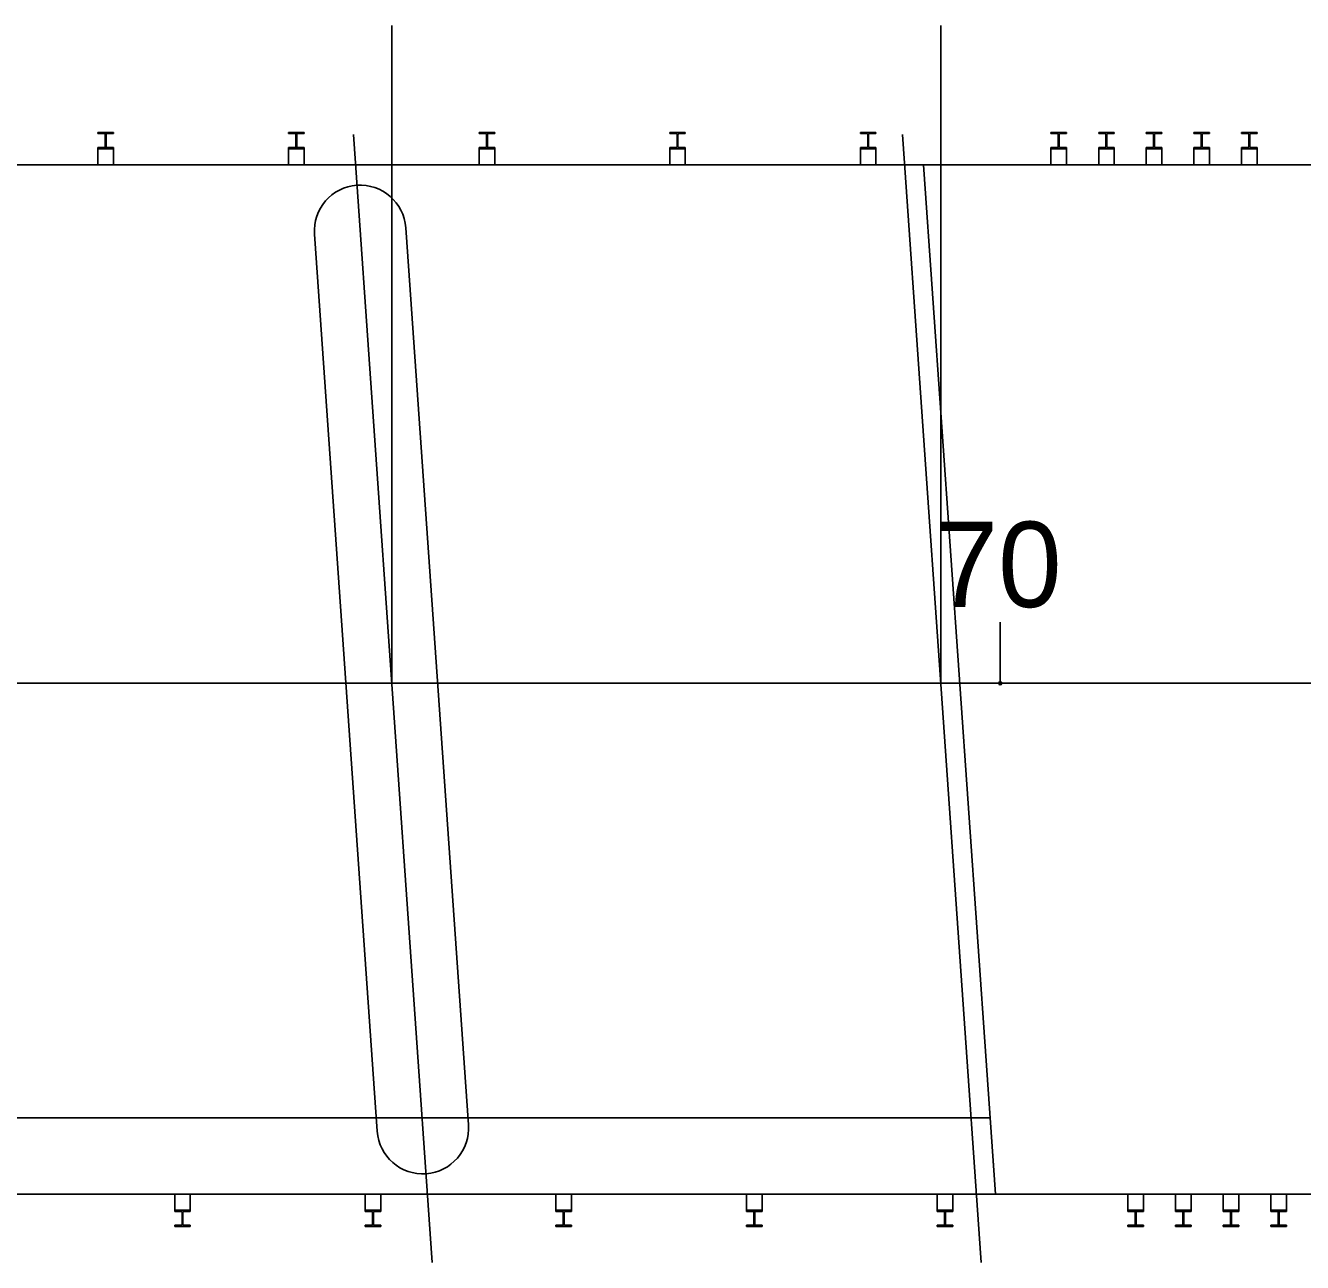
# Model space of a CAD drawing. Extents: x 27625 to 127752, y 6088 to 302357.
# Drawn here: x 27875.45 to 27917.32, y 6087.66 to 6128.23 of the extents above; entities that cross this region are included whole.
import ezdxf

# ---------------------------------------------------------------- set-up
doc = ezdxf.new("R2010")
doc.units = 0
for name, color, linetype in [('_CIVIL_CONSTRUCTION', 7, 'Continuous'), ('DR_X_Cells', 7, 'Continuous'), ('DV_X_Property_Line', 7, 'Continuous'), ('DV_X_Section_VMS_Line', 7, 'Continuous'), ('RS_Raster1', 7, 'Continuous'), ('RW_X_CL', 7, 'Continuous'), ('RW_X_CL_100_Bearings', 7, 'Continuous'), ('RW_X_CL_100_Curve_Data', 7, 'Continuous'), ('RW_X_CL_100_Stations', 7, 'Continuous'), ('RW_X_Fee_RW', 7, 'Continuous'), ('SV_X_Shot_Marker', 7, 'Continuous'), ('TopoDOT_Transients', 7, 'Continuous')]:
    doc.layers.add(name, color=color, linetype=linetype)

msp = doc.modelspace()

# ---------------------------------------------------------------- linework, layer by layer
at = {"layer": '_CIVIL_CONSTRUCTION'}
for p, q in [((27887.46, 6106.658), (27887.46, 6128.23)), ((27905.46, 6106.658), (27905.46, 6128.23))]:
    msp.add_line(p, q, dxfattribs=at)
at = {"layer": 'DR_X_Cells'}
msp.add_line((27907.411, 6106.658), (27907.411, 6108.658), dxfattribs=at)
msp.add_line((27907.411, 6106.658), (27907.411, 6108.658), dxfattribs=at)
at = {"layer": 'DV_X_Property_Line'}
for p, q in [((27904.895, 6123.658), (27845.148, 6123.658)), ((27907.255, 6089.908), (27847.508, 6089.908))]:
    msp.add_line(p, q, dxfattribs=at)
at = {"layer": 'DV_X_Section_VMS_Line'}
msp.add_line((27905.46, 6106.658), (27832.372, 6106.658), dxfattribs=at)
at = {"layer": 'RS_Raster1'}
msp.add_circle((27907.411, 6106.658), 0.05, dxfattribs=at)
at = {"layer": 'RW_X_CL'}
for p, q in [((27887.919, 6121.6), (27889.977, 6092.176)), ((27884.926, 6121.39), (27886.984, 6091.966))]:
    msp.add_line(p, q, dxfattribs=at)
for centre, start, end in [((27886.423, 6121.495), 4, 184), ((27888.48, 6092.071), 184, 4)]:
    msp.add_arc(centre, 1.5, start, end, dxfattribs=at)
at = {"layer": 'RW_X_CL_100_Bearings'}
for p, q in [((27904.895, 6123.658), (27907.255, 6089.908)), ((27904.895, 6123.658), (27919.895, 6123.658)), ((27907.255, 6089.908), (27922.255, 6089.908))]:
    msp.add_line(p, q, dxfattribs=at)
at = {"layer": 'RW_X_CL_100_Curve_Data'}
for p, q in [((27877.825, 6124.72), (27878.336, 6124.72)), ((27877.825, 6124.72), (27877.825, 6124.684)), ((27877.825, 6124.684), (27878.034, 6124.684)), ((27878.065, 6124.653), (27878.065, 6124.257)), ((27878.096, 6124.653), (27878.096, 6124.257)), ((27878.127, 6124.684), (27878.336, 6124.684)), ((27878.336, 6124.72), (27878.336, 6124.684)), ((27884.075, 6124.72), (27884.586, 6124.72)), ((27884.075, 6124.72), (27884.075, 6124.684)), ((27884.075, 6124.684), (27884.284, 6124.684)), ((27884.315, 6124.653), (27884.315, 6124.257)), ((27884.346, 6124.653), (27884.346, 6124.257)), ((27884.377, 6124.684), (27884.586, 6124.684)), ((27884.586, 6124.72), (27884.586, 6124.684)), ((27890.325, 6124.72), (27890.836, 6124.72)), ((27890.325, 6124.72), (27890.325, 6124.684)), ((27890.325, 6124.684), (27890.534, 6124.684)), ((27890.565, 6124.653), (27890.565, 6124.257)), ((27890.596, 6124.653), (27890.596, 6124.257)), ((27890.627, 6124.684), (27890.836, 6124.684)), ((27890.836, 6124.72), (27890.836, 6124.684)), ((27896.575, 6124.72), (27897.086, 6124.72)), ((27896.575, 6124.72), (27896.575, 6124.684)), ((27896.575, 6124.684), (27896.784, 6124.684)), ((27896.815, 6124.653), (27896.815, 6124.257)), ((27896.846, 6124.653), (27896.846, 6124.257)), ((27896.877, 6124.684), (27897.086, 6124.684)), ((27897.086, 6124.72), (27897.086, 6124.684)), ((27902.825, 6124.72), (27903.336, 6124.72)), ((27902.825, 6124.72), (27902.825, 6124.684)), ((27902.825, 6124.684), (27903.034, 6124.684)), ((27903.065, 6124.653), (27903.065, 6124.257)), ((27903.096, 6124.653), (27903.096, 6124.257)), ((27903.127, 6124.684), (27903.336, 6124.684)), ((27903.336, 6124.72), (27903.336, 6124.684)), ((27909.075, 6124.72), (27909.586, 6124.72)), ((27909.075, 6124.72), (27909.075, 6124.684)), ((27909.075, 6124.684), (27909.284, 6124.684)), ((27909.315, 6124.653), (27909.315, 6124.257)), ((27909.346, 6124.653), (27909.346, 6124.257)), ((27909.377, 6124.684), (27909.586, 6124.684)), ((27909.586, 6124.72), (27909.586, 6124.684)), ((27910.638, 6124.72), (27911.148, 6124.72)), ((27910.638, 6124.72), (27910.638, 6124.684)), ((27910.638, 6124.684), (27910.846, 6124.684)), ((27910.877, 6124.653), (27910.877, 6124.257)), ((27910.909, 6124.653), (27910.909, 6124.257)), ((27910.94, 6124.684), (27911.148, 6124.684)), ((27911.148, 6124.72), (27911.148, 6124.684)), ((27912.2, 6124.72), (27912.711, 6124.72)), ((27912.2, 6124.72), (27912.2, 6124.684)), ((27912.2, 6124.684), (27912.409, 6124.684)), ((27912.44, 6124.653), (27912.44, 6124.257)), ((27912.471, 6124.653), (27912.471, 6124.257)), ((27912.502, 6124.684), (27912.711, 6124.684)), ((27912.711, 6124.72), (27912.711, 6124.684)), ((27913.763, 6124.72), (27914.273, 6124.72)), ((27913.763, 6124.72), (27913.763, 6124.684)), ((27913.763, 6124.684), (27913.971, 6124.684)), ((27914.002, 6124.653), (27914.002, 6124.257)), ((27914.034, 6124.653), (27914.034, 6124.257)), ((27914.065, 6124.684), (27914.273, 6124.684)), ((27914.273, 6124.72), (27914.273, 6124.684)), ((27915.325, 6124.72), (27915.836, 6124.72)), ((27915.325, 6124.72), (27915.325, 6124.684)), ((27915.325, 6124.684), (27915.534, 6124.684)), ((27915.565, 6124.653), (27915.565, 6124.257)), ((27915.596, 6124.653), (27915.596, 6124.257)), ((27915.627, 6124.684), (27915.836, 6124.684)), ((27915.836, 6124.72), (27915.836, 6124.684)), ((27877.825, 6124.226), (27877.825, 6124.189)), ((27877.825, 6124.226), (27878.034, 6124.226)), ((27877.825, 6124.189), (27878.336, 6124.189)), ((27877.825, 6124.189), (27877.825, 6123.658)), ((27878.127, 6124.226), (27878.336, 6124.226)), ((27878.336, 6124.226), (27878.336, 6124.189)), ((27878.336, 6123.658), (27878.336, 6124.189)), ((27884.075, 6124.226), (27884.075, 6124.189)), ((27884.075, 6124.226), (27884.284, 6124.226)), ((27884.075, 6124.189), (27884.586, 6124.189)), ((27884.075, 6124.189), (27884.075, 6123.658)), ((27884.377, 6124.226), (27884.586, 6124.226)), ((27884.586, 6124.226), (27884.586, 6124.189)), ((27884.586, 6123.658), (27884.586, 6124.189)), ((27890.325, 6124.226), (27890.325, 6124.189)), ((27890.325, 6124.226), (27890.534, 6124.226)), ((27890.325, 6124.189), (27890.836, 6124.189)), ((27890.325, 6124.189), (27890.325, 6123.658)), ((27890.627, 6124.226), (27890.836, 6124.226)), ((27890.836, 6124.226), (27890.836, 6124.189)), ((27890.836, 6123.658), (27890.836, 6124.189)), ((27896.575, 6124.226), (27896.575, 6124.189)), ((27896.575, 6124.226), (27896.784, 6124.226)), ((27896.575, 6124.189), (27897.086, 6124.189)), ((27896.575, 6124.189), (27896.575, 6123.658)), ((27896.877, 6124.226), (27897.086, 6124.226)), ((27897.086, 6124.226), (27897.086, 6124.189)), ((27897.086, 6123.658), (27897.086, 6124.189)), ((27902.825, 6124.226), (27902.825, 6124.189)), ((27902.825, 6124.226), (27903.034, 6124.226)), ((27902.825, 6124.189), (27903.336, 6124.189)), ((27902.825, 6124.189), (27902.825, 6123.658)), ((27903.127, 6124.226), (27903.336, 6124.226)), ((27903.336, 6124.226), (27903.336, 6124.189)), ((27903.336, 6123.658), (27903.336, 6124.189)), ((27909.075, 6124.226), (27909.075, 6124.189)), ((27909.075, 6124.226), (27909.284, 6124.226)), ((27909.075, 6124.189), (27909.586, 6124.189)), ((27909.075, 6124.189), (27909.075, 6123.658)), ((27909.377, 6124.226), (27909.586, 6124.226)), ((27909.586, 6124.226), (27909.586, 6124.189)), ((27909.586, 6123.658), (27909.586, 6124.189)), ((27910.638, 6124.226), (27910.638, 6124.189)), ((27910.638, 6124.226), (27910.846, 6124.226)), ((27910.638, 6124.189), (27911.148, 6124.189)), ((27910.638, 6124.189), (27910.638, 6123.658)), ((27910.94, 6124.226), (27911.148, 6124.226)), ((27911.148, 6124.226), (27911.148, 6124.189)), ((27911.148, 6123.658), (27911.148, 6124.189)), ((27912.2, 6124.226), (27912.2, 6124.189)), ((27912.2, 6124.226), (27912.409, 6124.226)), ((27912.2, 6124.189), (27912.711, 6124.189)), ((27912.2, 6124.189), (27912.2, 6123.658)), ((27912.502, 6124.226), (27912.711, 6124.226)), ((27912.711, 6124.226), (27912.711, 6124.189)), ((27912.711, 6123.658), (27912.711, 6124.189)), ((27913.763, 6124.226), (27913.763, 6124.189)), ((27913.763, 6124.226), (27913.971, 6124.226)), ((27913.763, 6124.189), (27914.273, 6124.189)), ((27913.763, 6124.189), (27913.763, 6123.658)), ((27914.065, 6124.226), (27914.273, 6124.226)), ((27914.273, 6124.226), (27914.273, 6124.189)), ((27914.273, 6123.658), (27914.273, 6124.189)), ((27915.325, 6124.226), (27915.325, 6124.189)), ((27915.325, 6124.226), (27915.534, 6124.226)), ((27915.325, 6124.189), (27915.836, 6124.189)), ((27915.325, 6124.189), (27915.325, 6123.658)), ((27915.627, 6124.226), (27915.836, 6124.226)), ((27915.836, 6124.226), (27915.836, 6124.189)), ((27915.836, 6123.658), (27915.836, 6124.189)), ((27880.345, 6089.377), (27880.345, 6089.908)), ((27880.856, 6089.908), (27880.856, 6089.377)), ((27886.595, 6089.377), (27886.595, 6089.908)), ((27887.106, 6089.908), (27887.106, 6089.377)), ((27892.845, 6089.377), (27892.845, 6089.908)), ((27893.356, 6089.908), (27893.356, 6089.377)), ((27899.095, 6089.377), (27899.095, 6089.908)), ((27899.606, 6089.908), (27899.606, 6089.377)), ((27905.345, 6089.377), (27905.345, 6089.908)), ((27905.856, 6089.908), (27905.856, 6089.377)), ((27911.595, 6089.377), (27911.595, 6089.908)), ((27912.106, 6089.908), (27912.106, 6089.377)), ((27913.158, 6089.377), (27913.158, 6089.908)), ((27913.668, 6089.908), (27913.668, 6089.377)), ((27914.72, 6089.377), (27914.72, 6089.908)), ((27915.231, 6089.908), (27915.231, 6089.377)), ((27916.283, 6089.377), (27916.283, 6089.908)), ((27916.793, 6089.908), (27916.793, 6089.377)), ((27880.345, 6089.377), (27880.856, 6089.377)), ((27880.345, 6089.34), (27880.345, 6089.377)), ((27880.345, 6089.34), (27880.554, 6089.34)), ((27880.585, 6088.913), (27880.585, 6089.309)), ((27880.616, 6088.913), (27880.616, 6089.309)), ((27880.647, 6089.34), (27880.856, 6089.34)), ((27880.856, 6089.34), (27880.856, 6089.377)), ((27886.595, 6089.377), (27887.106, 6089.377)), ((27886.595, 6089.34), (27886.595, 6089.377)), ((27886.595, 6089.34), (27886.804, 6089.34)), ((27886.835, 6088.913), (27886.835, 6089.309)), ((27886.866, 6088.913), (27886.866, 6089.309)), ((27886.897, 6089.34), (27887.106, 6089.34)), ((27887.106, 6089.34), (27887.106, 6089.377)), ((27892.845, 6089.377), (27893.356, 6089.377)), ((27892.845, 6089.34), (27892.845, 6089.377)), ((27892.845, 6089.34), (27893.054, 6089.34)), ((27893.085, 6088.913), (27893.085, 6089.309)), ((27893.116, 6088.913), (27893.116, 6089.309)), ((27893.147, 6089.34), (27893.356, 6089.34)), ((27893.356, 6089.34), (27893.356, 6089.377)), ((27899.095, 6089.377), (27899.606, 6089.377)), ((27899.095, 6089.34), (27899.095, 6089.377)), ((27899.095, 6089.34), (27899.304, 6089.34)), ((27899.335, 6088.913), (27899.335, 6089.309)), ((27899.366, 6088.913), (27899.366, 6089.309)), ((27899.397, 6089.34), (27899.606, 6089.34)), ((27899.606, 6089.34), (27899.606, 6089.377)), ((27905.345, 6089.377), (27905.856, 6089.377)), ((27905.345, 6089.34), (27905.345, 6089.377)), ((27905.345, 6089.34), (27905.554, 6089.34)), ((27905.585, 6088.913), (27905.585, 6089.309)), ((27905.616, 6088.913), (27905.616, 6089.309)), ((27905.647, 6089.34), (27905.856, 6089.34)), ((27905.856, 6089.34), (27905.856, 6089.377)), ((27911.595, 6089.377), (27912.106, 6089.377)), ((27911.595, 6089.34), (27911.595, 6089.377)), ((27911.595, 6089.34), (27911.804, 6089.34)), ((27911.835, 6088.913), (27911.835, 6089.309)), ((27911.866, 6088.913), (27911.866, 6089.309)), ((27911.897, 6089.34), (27912.106, 6089.34)), ((27912.106, 6089.34), (27912.106, 6089.377)), ((27913.158, 6089.377), (27913.668, 6089.377)), ((27913.158, 6089.34), (27913.158, 6089.377)), ((27913.158, 6089.34), (27913.366, 6089.34)), ((27913.397, 6088.913), (27913.397, 6089.309)), ((27913.429, 6088.913), (27913.429, 6089.309)), ((27913.46, 6089.34), (27913.668, 6089.34)), ((27913.668, 6089.34), (27913.668, 6089.377)), ((27914.72, 6089.377), (27915.231, 6089.377)), ((27914.72, 6089.34), (27914.72, 6089.377)), ((27914.72, 6089.34), (27914.929, 6089.34)), ((27914.96, 6088.913), (27914.96, 6089.309)), ((27914.991, 6088.913), (27914.991, 6089.309)), ((27915.022, 6089.34), (27915.231, 6089.34)), ((27915.231, 6089.34), (27915.231, 6089.377)), ((27916.283, 6089.377), (27916.793, 6089.377)), ((27916.283, 6089.34), (27916.283, 6089.377)), ((27916.283, 6089.34), (27916.491, 6089.34)), ((27916.522, 6088.913), (27916.522, 6089.309)), ((27916.554, 6088.913), (27916.554, 6089.309)), ((27916.585, 6089.34), (27916.793, 6089.34)), ((27916.793, 6089.34), (27916.793, 6089.377)), ((27880.345, 6088.846), (27880.345, 6088.882)), ((27880.345, 6088.882), (27880.554, 6088.882)), ((27880.345, 6088.846), (27880.856, 6088.846)), ((27880.647, 6088.882), (27880.856, 6088.882)), ((27880.856, 6088.846), (27880.856, 6088.882)), ((27886.595, 6088.846), (27886.595, 6088.882)), ((27886.595, 6088.882), (27886.804, 6088.882)), ((27886.595, 6088.846), (27887.106, 6088.846)), ((27886.897, 6088.882), (27887.106, 6088.882)), ((27887.106, 6088.846), (27887.106, 6088.882)), ((27892.845, 6088.846), (27892.845, 6088.882)), ((27892.845, 6088.882), (27893.054, 6088.882)), ((27892.845, 6088.846), (27893.356, 6088.846)), ((27893.147, 6088.882), (27893.356, 6088.882)), ((27893.356, 6088.846), (27893.356, 6088.882)), ((27899.095, 6088.846), (27899.095, 6088.882)), ((27899.095, 6088.882), (27899.304, 6088.882)), ((27899.095, 6088.846), (27899.606, 6088.846)), ((27899.397, 6088.882), (27899.606, 6088.882)), ((27899.606, 6088.846), (27899.606, 6088.882)), ((27905.345, 6088.846), (27905.345, 6088.882)), ((27905.345, 6088.882), (27905.554, 6088.882)), ((27905.345, 6088.846), (27905.856, 6088.846)), ((27905.647, 6088.882), (27905.856, 6088.882)), ((27905.856, 6088.846), (27905.856, 6088.882)), ((27911.595, 6088.846), (27911.595, 6088.882)), ((27911.595, 6088.882), (27911.804, 6088.882)), ((27911.595, 6088.846), (27912.106, 6088.846)), ((27911.897, 6088.882), (27912.106, 6088.882)), ((27912.106, 6088.846), (27912.106, 6088.882)), ((27913.158, 6088.846), (27913.158, 6088.882)), ((27913.158, 6088.882), (27913.366, 6088.882)), ((27913.158, 6088.846), (27913.668, 6088.846)), ((27913.46, 6088.882), (27913.668, 6088.882)), ((27913.668, 6088.846), (27913.668, 6088.882)), ((27914.72, 6088.846), (27914.72, 6088.882)), ((27914.72, 6088.882), (27914.929, 6088.882)), ((27914.72, 6088.846), (27915.231, 6088.846)), ((27915.022, 6088.882), (27915.231, 6088.882)), ((27915.231, 6088.846), (27915.231, 6088.882)), ((27916.283, 6088.846), (27916.283, 6088.882)), ((27916.283, 6088.882), (27916.491, 6088.882)), ((27916.283, 6088.846), (27916.793, 6088.846)), ((27916.585, 6088.882), (27916.793, 6088.882)), ((27916.793, 6088.846), (27916.793, 6088.882))]:
    msp.add_line(p, q, dxfattribs=at)
for centre, start, end in [((27878.034, 6124.653), 0, 90), ((27878.128, 6124.653), 90, 180), ((27884.284, 6124.653), 0, 90), ((27884.378, 6124.653), 90, 180), ((27890.534, 6124.653), 0, 90), ((27890.628, 6124.653), 90, 180), ((27896.784, 6124.653), 0, 90), ((27896.878, 6124.653), 90, 180), ((27903.034, 6124.653), 0, 90), ((27903.128, 6124.653), 90, 180), ((27909.284, 6124.653), 0, 90), ((27909.378, 6124.653), 90, 180), ((27910.846, 6124.653), 0, 90), ((27910.94, 6124.653), 90, 180), ((27912.409, 6124.653), 0, 90), ((27912.503, 6124.653), 90, 180), ((27913.971, 6124.653), 0, 90), ((27914.065, 6124.653), 90, 180), ((27915.534, 6124.653), 0, 90), ((27915.628, 6124.653), 90, 180), ((27878.034, 6124.257), 270, 0), ((27878.128, 6124.257), 180, 270), ((27884.284, 6124.257), 270, 0), ((27884.378, 6124.257), 180, 270), ((27890.534, 6124.257), 270, 0), ((27890.628, 6124.257), 180, 270), ((27896.784, 6124.257), 270, 0), ((27896.878, 6124.257), 180, 270), ((27903.034, 6124.257), 270, 0), ((27903.128, 6124.257), 180, 270), ((27909.284, 6124.257), 270, 0), ((27909.378, 6124.257), 180, 270), ((27910.846, 6124.257), 270, 0), ((27910.94, 6124.257), 180, 270), ((27912.409, 6124.257), 270, 0), ((27912.503, 6124.257), 180, 270), ((27913.971, 6124.257), 270, 0), ((27914.065, 6124.257), 180, 270), ((27915.534, 6124.257), 270, 0), ((27915.628, 6124.257), 180, 270), ((27880.554, 6089.309), 0, 90), ((27880.648, 6089.309), 90, 180), ((27886.804, 6089.309), 0, 90), ((27886.898, 6089.309), 90, 180), ((27893.054, 6089.309), 0, 90), ((27893.148, 6089.309), 90, 180), ((27899.304, 6089.309), 0, 90), ((27899.398, 6089.309), 90, 180), ((27905.554, 6089.309), 0, 90), ((27905.648, 6089.309), 90, 180), ((27911.804, 6089.309), 0, 90), ((27911.898, 6089.309), 90, 180), ((27913.366, 6089.309), 0, 90), ((27913.46, 6089.309), 90, 180), ((27914.929, 6089.309), 0, 90), ((27915.023, 6089.309), 90, 180), ((27916.491, 6089.309), 0, 90), ((27916.585, 6089.309), 90, 180), ((27880.554, 6088.913), 270, 0), ((27880.648, 6088.913), 180, 270), ((27886.804, 6088.913), 270, 0), ((27886.898, 6088.913), 180, 270), ((27893.054, 6088.913), 270, 0), ((27893.148, 6088.913), 180, 270), ((27899.304, 6088.913), 270, 0), ((27899.398, 6088.913), 180, 270), ((27905.554, 6088.913), 270, 0), ((27905.648, 6088.913), 180, 270), ((27911.804, 6088.913), 270, 0), ((27911.898, 6088.913), 180, 270), ((27913.366, 6088.913), 270, 0), ((27913.46, 6088.913), 180, 270), ((27914.929, 6088.913), 270, 0), ((27915.023, 6088.913), 180, 270), ((27916.491, 6088.913), 270, 0), ((27916.585, 6088.913), 180, 270)]:
    msp.add_arc(centre, 0.0312, start, end, dxfattribs=at)
at = {"layer": 'RW_X_CL_100_Stations'}
for p, q in [((27877.825, 6123.658), (27878.336, 6123.658)), ((27884.075, 6123.658), (27884.586, 6123.658)), ((27909.075, 6123.658), (27909.586, 6123.658)), ((27910.638, 6123.658), (27911.148, 6123.658)), ((27912.2, 6123.658), (27912.711, 6123.658)), ((27913.763, 6123.658), (27914.273, 6123.658)), ((27915.325, 6123.658), (27915.836, 6123.658)), ((27880.345, 6089.908), (27880.856, 6089.908)), ((27886.595, 6089.908), (27887.106, 6089.908)), ((27911.595, 6089.908), (27912.106, 6089.908)), ((27913.158, 6089.908), (27913.668, 6089.908)), ((27914.72, 6089.908), (27915.231, 6089.908)), ((27916.283, 6089.908), (27916.793, 6089.908))]:
    msp.add_line(p, q, dxfattribs=at)
at = {"layer": 'RW_X_Fee_RW'}
for p, q in [((27886.202, 6124.655), (27888.788, 6087.664)), ((27904.202, 6124.655), (27906.788, 6087.664))]:
    msp.add_line(p, q, dxfattribs=at)
at = {"layer": 'SV_X_Shot_Marker'}
msp.add_line((27857.78, 6106.658), (28207.41, 6106.658), dxfattribs=at)
at = {"layer": 'TopoDOT_Transients'}
for p, q in [((27907.08, 6092.408), (27847.333, 6092.408)), ((27907.08, 6092.408), (27907.255, 6089.908)), ((27907.255, 6089.908), (27847.508, 6089.908))]:
    msp.add_line(p, q, dxfattribs=at)

# ---------------------------------------------------------------- texts
at = {"layer": 'DR_X_Cells'}
msp.add_text('70', height=2.8, dxfattribs=at).set_placement((27905.26, 6109.158))
msp.add_text('70', height=2.8, rotation=360, dxfattribs=at).set_placement((27905.26, 6109.158))

doc.saveas('drawing.dxf')
